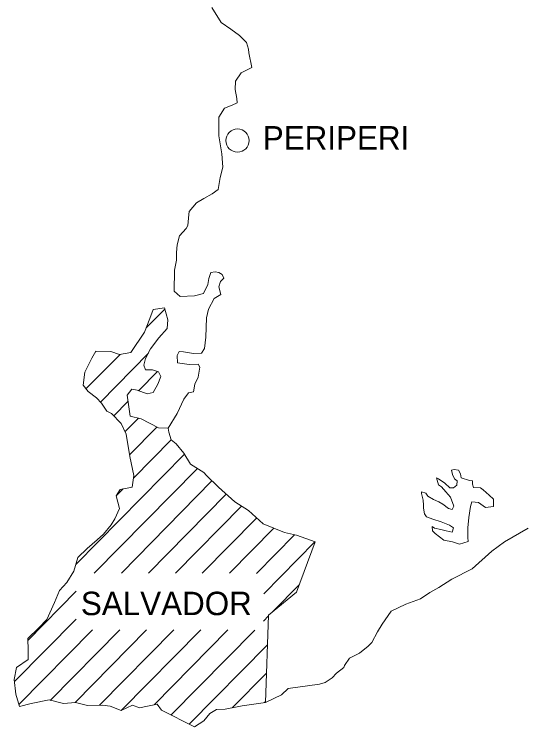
# Model space of a CAD drawing. Extents: x 47169 to 972804, y 7447977 to 9608469.
# Drawn here: x 550287 to 564823, y 8560772 to 8580999 of the extents above; entities that cross this region are included whole.
import ezdxf

# ---------------------------------------------------------------- set-up
doc = ezdxf.new("R2010")
doc.units = 0
doc.header["$LTSCALE"] = 270
doc.layers.add('1', color=7, linetype='Continuous', lineweight=13)
doc.layers.add('2', color=7, linetype='Continuous', lineweight=13)
doc.layers.add('3', color=7, linetype='Continuous')

msp = doc.modelspace()

# ---------------------------------------------------------------- linework, layer by layer
at = {"layer": '1'}
for p, q in [((554026.6, 8572099.4), (554559.2, 8572629.2)), ((552320.1, 8570366.3), (553287.4, 8571337.7)), ((552593.3, 8571416.4), (552615, 8571438.5)), ((552731.6, 8569989.6), (554090.3, 8571380.4)), ((553817, 8570319.2), (554349.7, 8570860.1)), ((553110.6, 8569601.8), (553512.7, 8570010.2)), ((553424.3, 8569147.7), (553815.5, 8569534.1)), ((553553.2, 8568495), (554335.7, 8569278.7)), ((553671.2, 8567831.2), (554736.3, 8568912.9)), ((552039.6, 8565390.3), (555115.2, 8568514.1)), ((552554.7, 8565136.4), (555483.2, 8568104.1)), ((553325.5, 8565134.9), (555894.7, 8567749.4)), ((553193, 8567345.5), (553377.7, 8567522.1)), ((554090.6, 8565133.5), (556295.2, 8567372.6)), ((554860.6, 8565131.9), (556739.3, 8567039.9)), ((555619.8, 8565130.4), (557161.6, 8566696.2)), ((556389.8, 8565128.9), (557649.1, 8566407.7)), ((557159.9, 8565127.3), (558234.4, 8566218.4)), ((557363.1, 8564550), (558808.8, 8566018.1)), ((550669, 8563225.2), (552045.2, 8564620.1)), ((557633.3, 8564052.1), (558372.4, 8564802.6)), ((550298.1, 8562053.6), (552039.2, 8563825.8)), ((557356.2, 8563770.6), (557502.9, 8563919.6)), ((550416.2, 8561400.9), (552509.7, 8563527.7)), ((551305.7, 8561520.9), (553279.7, 8563526.2)), ((552010.5, 8561464.3), (554038.9, 8563524.7)), ((552704.4, 8561385.6), (554808.9, 8563523.2)), ((553322.2, 8561229.6), (555578.9, 8563521.7)), ((554255.2, 8561393.6), (556348.9, 8563520.1)), ((554731.7, 8561105.2), (557108, 8563518.5)), ((555251.8, 8560849.8), (557468.7, 8563101.3)), ((556467.3, 8561311.8), (557445.3, 8562294)), ((557389.4, 8561464.7), (557411.1, 8561486.8))]:
    msp.add_line(p, q, dxfattribs=at)
for points in [[(555889.1, 8581186.3), (556159.6, 8580765.5), (556430.5, 8580576.9), (556679.7, 8580399.5), (556874.6, 8580200), (556928.5, 8580011.9), (556939.1, 8579901.3), (557025.1, 8579492), (556721, 8579337.7), (556557.7, 8579094.8), (556557.2, 8578862.5), (556600.1, 8578608.1), (556610.7, 8578486.4), (556469.5, 8578420.3), (556252.3, 8578332.3), (556089, 8578078.3), (556088, 8577547.4), (556173.8, 8577038.6), (556194.9, 8576784.2), (556205.6, 8576662.5), (556129, 8576364), (556074.1, 8576021.3), (555900.2, 8575900), (555661.2, 8575767.8), (555454.8, 8575646.5), (555248.2, 8575403.7), (555237.2, 8575315.2), (555214.9, 8575005.6), (555160.5, 8574917.2), (554975.6, 8574707.5), (554910, 8574453.2), (554887.9, 8574232.1), (554887.4, 8574022), (554832.6, 8573734.5), (554820.6, 8573137.4), (554993.9, 8572982.2), (555395.3, 8573003.5), (555655.8, 8573069.4), (555775.7, 8573323.5), (555808.6, 8573500.4), (555863.2, 8573666.1), (555982.6, 8573688), (556091, 8573665.7), (556188.6, 8573610.2), (556231.8, 8573510.6), (556133.9, 8573411.2), (556090.2, 8573256.5), (556144, 8573046.3), (555959.3, 8572925), (555796, 8572626.7), (555741.3, 8572383.5), (555718.5, 8571830.6), (555685.3, 8571510), (555598.2, 8571377.4), (555370.4, 8571366.8), (555088.4, 8571411.6), (554969.1, 8571422.9), (554903.8, 8571312.4), (554914.2, 8571102.3), (555250.4, 8571057.4), (555500, 8571068), (555554, 8570979.4), (555499.2, 8570691.9), (555412, 8570493.1), (555368.2, 8570283), (555227.1, 8570250.1), (555096.6, 8570073.4), (554911.4, 8569664.6), (554650.2, 8569244.9), (554671.7, 8569134.2), (554736.3, 8568912.9), (554877.2, 8568802.1), (555093.6, 8568536.2), (555288.2, 8568226.2), (555667.4, 8567993.2), (555743.1, 8567904.6), (556078.7, 8567572.1), (556544.3, 8567161.9), (556934.3, 8566906.8), (557345.7, 8566529.9), (557952.5, 8566285.4), (558288.6, 8566207.2), (558819.7, 8566018.1), (558296.1, 8564592.6), (557503, 8563941.7), (557411.1, 8561464.7), (556749.3, 8561366.5), (556272, 8561267.9), (556022.5, 8561257.4), (555838, 8561147.2), (555664, 8560937.4), (555403.4, 8560772), (554460.9, 8561238.4), (554342, 8561415.6), (553842.9, 8561306)], [(553842.9, 8561306), (553637, 8561383.8), (553322.2, 8561229.6), (553008, 8561351.8), (552791.2, 8561385.4), (552368.2, 8561375.2), (552021.3, 8561464.3), (551685.1, 8561431.8), (551273.2, 8561532.1), (550763.3, 8561433.5), (550437.8, 8561345.6), (550330, 8561699.7), (550287.4, 8562108.9), (550353.1, 8562451.7), (550678.9, 8562683.3), (550679.3, 8562948.7), (550669.1, 8563280.5), (550973.3, 8563567.5), (551212.4, 8563821.4), (551430.2, 8564296.6), (551571.8, 8564639.1), (551778.3, 8564871), (551974.1, 8565191.3), (552094.2, 8565578.2), (552354.9, 8565832), (552637.4, 8566074.8), (552822.1, 8566240.3), (553039.6, 8566505.3), (553137.5, 8566671), (553268.2, 8566969.4), (553182.1, 8567323.4), (553290.9, 8567511.2), (553627.3, 8567576.9), (553682.2, 8567908.6), (553563.9, 8568439.7), (553456.7, 8569081.3), (553316.2, 8569380.2), (553045.6, 8569668.2), (552915.6, 8569734.8), (552764.1, 8569956.3), (552623.4, 8570111.4), (552385.1, 8570288.8), (552244.4, 8570466), (552288.5, 8570841.9), (552484.5, 8571239.7), (552604.2, 8571438.6), (553027.2, 8571426.7), (553276.6, 8571337.7), (553591.3, 8571392.4), (553983, 8571977.8), (554135.6, 8572364.6), (554222.9, 8572618.8), (554548.4, 8572662.4), (554645.4, 8572319.3), (554623.2, 8572076.1), (554384.1, 8571811.1), (554155.6, 8571501.9), (554014.1, 8571225.7), (553959.5, 8571037.8), (554013.4, 8570905), (554208.7, 8570904.6), (554382.2, 8570849), (554447, 8570716.2), (554359.8, 8570495.1), (554229.2, 8570263.2), (554055.5, 8570219.3), (553773.7, 8570330.4), (553621.8, 8570352.8), (553491.3, 8570187.2), (553577, 8569589.8), (553891.4, 8569511.8), (554379.1, 8569256.5), (554650.2, 8569244.9)], [(557411.1, 8561464.7), (557867, 8561673.8), (558051.7, 8561861.5), (558941.2, 8561981.2), (559104, 8562025.1), (559299.5, 8562157.4), (559429.9, 8562289.8), (559636.3, 8562455.3), (559658.1, 8562510.5), (559799.6, 8562720.3), (560081.9, 8562863.5), (560320.9, 8563062.1), (560429.6, 8563161.4), (560592.9, 8563470.7), (560723.5, 8563680.5), (560973.8, 8564056), (561397.2, 8564254.1), (561809.7, 8564408), (562070.4, 8564584.4), (562331, 8564727.6), (562700.3, 8564959), (563275.8, 8565256.3), (563830.1, 8565752.7), (564188.7, 8566017.2), (564862.1, 8566413.8)]]:
    msp.add_lwpolyline(points, dxfattribs=at)
msp.add_lwpolyline([(563181.5, 8566716.3), (563148.3, 8566417.8), (563147.7, 8566141.3), (563158.3, 8566030.7), (562919.5, 8565953.8), (562713.6, 8566020.6), (562475, 8566065.4), (562345.1, 8566165.2), (562226, 8566254), (562150.2, 8566331.6), (562139.7, 8566453.2), (562204.6, 8566408.8), (562389, 8566375.3), (562540.7, 8566330.7), (562703.3, 8566297.1), (562747, 8566418.7), (562627.8, 8566496.4), (562400.3, 8566585.4), (562161.8, 8566663.3), (561977.6, 8566730.1), (561923.5, 8566818.7), (561891.4, 8566973.6), (561891.6, 8567062.1), (561881, 8567205.8), (561838.1, 8567393.9), (561838.2, 8567438.2), (561957.4, 8567404.8), (562022.3, 8567316.1), (562173.9, 8567227.3), (562325.6, 8567160.6), (562444.8, 8567094), (562607.2, 8566972), (562704.8, 8566938.6), (562759.2, 8567038), (562662.2, 8567292.6), (562532.3, 8567436.6), (562402.5, 8567580.7), (562315.9, 8567636.2), (562262.1, 8567835.4), (562316.3, 8567813.1), (562500.4, 8567691.1), (562641.1, 8567558.1), (562749.6, 8567557.8), (562836.5, 8567635), (562847.6, 8567756.7), (562771.8, 8567812.1), (562717.9, 8567933.9), (562685.6, 8568055.6), (562761.6, 8568077.6), (562891.7, 8568055.1), (562945.7, 8567955.5), (562967.1, 8567833.8), (563194.8, 8567766.9), (563281.5, 8567755.7), (563281.3, 8567656.1), (563313.6, 8567567.6), (563508.9, 8567556.1), (563584.7, 8567500.6), (563757.8, 8567345.4), (563876.9, 8567234.5), (563876.4, 8567024.4), (563648.6, 8566991.7), (563453.7, 8567135.9), (563269.3, 8567158.5), (563225.6, 8567025.9)], close=True, dxfattribs=at)
at = {"layer": '2'}
msp.add_circle((556619.4, 8577413.7), 328.4, dxfattribs=at)

# ---------------------------------------------------------------- texts
at = {"layer": '3'}
for s, height, p in [('PERIPERI', 666, (557335, 8577157.8)), ('SALVADOR', 665.7, (552176.7, 8563939.8))]:
    msp.add_text(s, height=height, dxfattribs=at).set_placement(p)

doc.saveas('drawing.dxf')
